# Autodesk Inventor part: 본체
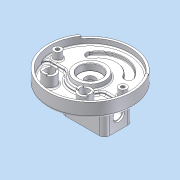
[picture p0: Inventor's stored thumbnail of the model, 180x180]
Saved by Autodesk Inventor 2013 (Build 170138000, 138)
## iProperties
Company: 한국ATC센터
Created: 2015-04
Part Number: 본체
Document SubType Name: Modeling
Designer: KYOUNG IL JANG
Density: 2.71 g/cm^3
Material: 알루미늄 6061
Mass: 1340.83 g
Surface Area: 1387.34 cm^2
Volume: 494.771 cm^3
Author: KYOUNG IL JANG
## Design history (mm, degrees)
sketch "스케치1"
  geometry: L1 (-59, -19)-(-59, 19); L2 (59, 19)-(59, -19); L3 (-41, 19)-(-41, -19); L4 (41, -19)-(41, 19); L5 (38.527, 33.023)-(55.442, 39.179); L6 (-38.527, 33.023)-(-55.442, 39.179); C1 r 90 at (0, 0); C2 r 95 at (0, 0); A1 r 59 centre (0, 19) between (59, 19) and (-59, 19); A2 r 59 centre (0, -19) between (-59, -19) and (59, -19); A3 r 41 centre (0, -19) between (-41, -19) and (41, -19); A4 r 41 centre (0, 19) between (41, 19) and (-41, 19); 2 further points
  constraints: 12 end point, 12 point on circle, 6 centre point, 4 tangent, 2 parallel, 2 point on line, 1 coincident, 1 horizontal alignment, 1 midpoint, 1 vertical, 1 vertical alignment, 3 other
  dimensions: "d2" = 180 diameter of C1; "d3" = 156 dimension on A2 A1; "d4" = 118 distance between parallel lines of L2 L1; "d5" = 18 distance between parallel lines of L2 L4; "d8" = 190 diameter of C2; "d124" = 110 deg dimension on A1.centre point (0, 0) L5.end; "d125" = 140 deg angle of L5 L6
extrude "돌출1" new body sketch "스케치1" distance "d6" = 14; taper "d7" = 0 deg
extrude "돌출2" join sketch "스케치1" distance "d9" = 13; taper "d10" = 0 deg
extrude "돌출3" cut sketch "스케치1" distance "d11" = 7; taper "d12" = 0 deg
sketch "스케치2"
  geometry: C1 r 11.5 at (0, 0); 1 further point
  constraints: 1 centre point, 1 coincident
  dimensions: "d13" = 23 diameter of C1
extrude "돌출4" cut sketch "스케치2" stored distance "d14" = 7; taper "d15" = 0 deg
fillet "모깎기1"
fillet "모깎기2"
sketch "스케치3"
  geometry: L1 (-73.724, 51.622)-(-77.819, 54.49); L2 (73.724, 51.622)-(77.819, 54.49); L3 (0, 0)-(0, -90); A1 r 95 centre (0, 0) between (-77.819, 54.49) and (77.819, 54.49) reference; A2 r 90 centre (0, 0) between (-73.724, 51.622) and (73.724, 51.622) reference; 1 further point
  constraints: 6 end point, 5 point on circle, 1 point on line, 1 vertical, 1 other
  dimensions: "d16" = 250 deg dimension on L2 L1
extrude "돌출5" join sketch "스케치3" distance "d17" = 5; taper "d18" = 0 deg
hole "구멍1" diameter "d21" = 50; stored, may be unused: countersink angle "d25" = 90 deg, drill point angle "d27" = 0 deg; dims "d19" = 10, "d20" = 10, "d22" = 6, "d23" = 4, "d24" = 2, "d26" = 5
fillet "모깎기3" dims "d28" = 0.3
fillet "모깎기5" dims "d30" = 3
sketch "스케치4"
  geometry: C1 r 35 at (0, 0); C2 r 25 at (0, 0); 1 further point
  constraints: 2 centre point, 1 coincident
  dimensions: "d32" = 70 diameter of C1 (derived); "d36" = 10 radial gap between concentric circles of C1 C2
extrude "돌출6" join sketch "스케치4" distance "d33" = 10; taper "d34" = 0 deg
feature "면 기울기2" dims angle "d37" = 10 deg
chamfer "모따기1" distance "d39" = 1; stored, may be unused: second distance "d40" = 2, angle "d41" = 45 deg
fillet "모깎기7" dims "d42" = 5
sketch "스케치5"
  geometry: L1 (-40.249, -12)-(-89.196, -12); L2 (40.249, -12)-(89.196, -12); A1 r 90 centre (0, 0) between (-89.196, -12) and (89.196, -12) reference; A2 r 42 centre (0, 0) between (-40.249, -12) and (40.249, -12); 1 further point
  constraints: 4 end point, 4 point on circle, 1 centre point, 1 collinear, 1 horizontal, 1 point on line
  dimensions: "d43" = 48 radial gap between concentric circles of A1 A2; "d44" = 12 distance from line of point (0, 0) L1
extrude "돌출7" cut sketch "스케치5" stored distance "d45" = 10; taper "d46" = 0 deg
fillet "모깎기8" dims "d47" = 10
chamfer "모따기2" distance "d49" = 1; stored, may be unused: second distance "d50" = 2, angle "d51" = 45 deg
sketch "스케치8"
  geometry: C1 r 9 at (74, 0); C2 r 9 at (-74, 0); A1 r 74 centre (0, 0) between (74, 0) and (-74, 0); 1 further point
  constraints: 3 centre point, 2 horizontal alignment, 2 point on circle, 1 coincident, 1 equal radius
  dimensions: "d64" = 18 diameter of C1; "d65" = 148 diameter of A1
extrude "돌출9" join sketch "스케치8" stored distance "d66" = 5; taper "d67" = 0 deg
sketch "스케치11"
  geometry: C1 r 15 at (40, -52); C2 r 15 at (-40, -52); 1 further point
  constraints: 2 centre point, 1 equal radius, 1 horizontal alignment
  dimensions: "d82" = 52 vertical distance of point (0, 0) C1.centre; "d83" = 30 diameter of C1; "d84" = 80 distance of C2.centre C1.centre; "d85" = 40 horizontal distance of point (0, 0) C1.centre (= 0.5 x d84)
extrude "돌출10" join sketch "스케치11" stored distance "d86" = 10; taper "d87" = 0 deg
node "구멍3"
node "구멍5"
hole "구멍6" diameter "d92" = 20; stored, may be unused: countersink angle "d96" = 90 deg, drill point angle "d98" = 118 deg; dims "d90" = 10, "d91" = 10, "d93" = 6, "d94" = 4, "d95" = 2, "d97" = 8
hole "구멍7" diameter "d101" = 20; stored, may be unused: countersink angle "d105" = 90 deg, drill point angle "d107" = 118 deg; dims "d99" = 10, "d100" = 10, "d102" = 6, "d103" = 4, "d104" = 2, "d106" = 8
fillet "모깎기13" dims "d108" = 3
sketch "스케치13"
  geometry: L1 (-20.252, -58)-(-26, -58); L2 (-42, -58)-(-47.748, -58); L3 (-20.252, -46)-(-26, -46); L4 (-42, -46)-(-47.748, -46); L5 (-108, -65.748)-(-108, -60); L6 (-108, -44)-(-108, -38.252); L7 (-120, -44)-(-120, -38.252); L8 (-120, -60)-(-120, -65.748); A1 r 15 centre (-34, -52) between (-20.252, -58) and (-47.748, -58) reference; A2 r 10 centre (-34, -52) between (-26, -58) and (-42, -58) reference; A3 r 15 centre (-114, -52) between (-108, -65.748) and (-108, -38.252) reference; A4 r 10 centre (-114, -52) between (-108, -60) and (-108, -44) reference; 1 further point
  constraints: 16 end point, 16 point on circle, 3 equal length, 3 point on line, 2 collinear, 1 horizontal, 1 perpendicular
  dimensions: "d114" = 12 distance between parallel lines of L4 L2; "d115" = 6 distance from line of A1.centre L2 (= 0.5 x d114); "d116" = 12 distance between parallel lines of L8 L5 (= d114); "d117" = 6 distance from line of A3.centre L5 (= d115)
extrude "돌출12" join sketch "스케치13" distance "d118" = 3; taper "d119" = 0 deg
fillet "모깎기14" dims "d120" = 1
sketch "스케치14"
  geometry: L1 (23, 32.5)-(-53, 32.5); L2 (-65, 20.5)-(-65, -20.5); L3 (-53, -32.5)-(23, -32.5); L4 (35, -20.5)-(35, 20.5); L5 (30, 20.5)-(30, -20.5); L6 (23, -27.5)-(-53, -27.5); L7 (-60, -20.5)-(-60, 20.5); L8 (-53, 27.5)-(23, 27.5); A1 r 12 centre (-53, -20.5) between (-65, -20.5) and (-53, -32.5); A2 r 12 centre (-53, 20.5) between (-53, 32.5) and (-65, 20.5); A3 r 12 centre (23, 20.5) between (35, 20.5) and (23, 32.5); A4 r 12 centre (23, -20.5) between (23, -32.5) and (35, -20.5); A5 r 7 centre (23, -20.5) between (23, -27.5) and (30, -20.5); A6 r 7 centre (-53, -20.5) between (-60, -20.5) and (-53, -27.5); A7 r 7 centre (-53, 20.5) between (-53, 27.5) and (-60, 20.5); A8 r 7 centre (23, 20.5) between (30, 20.5) and (23, 27.5); A9 r 6 centre (-23, -25) between (-17.546, -27.5) and (-28.454, -27.5); A10 r 6 centre (-23, 25) between (-28.454, 27.5) and (-17.546, 27.5); 6 further points
  constraints: 20 point on circle, 16 end point, 12 point on line, 10 centre point, 8 tangent, 4 equal radius, 4 parallel, 2 perpendicular, 1 horizontal, 1 horizontal alignment, 1 midpoint, 1 vertical alignment, 7 other
  dimensions: "d126" = 35 distance from line of point (0, 0) L4; "d127" = 65 distance of point (35, -32.5) point (35, 32.5); "d128" = 100 distance of point (35, 32.5) point (-65, 32.5); "d132" = 12 radius of A1; "d133" = 5 distance between parallel lines of L5 L4; "d141" = 42 distance from line of A9.centre L2; "d142" = 12 diameter of A9; "d143" = 50 distance of A10.centre A9.centre; "d144" = 25 vertical distance of point (0, 0) A9.centre (= 0.5 x d143)
extrude "돌출13" join sketch "스케치14" distance "d130" = 58; taper "d131" = 0 deg
fillet "모깎기16" dims "d145" = 3
hole "구멍8" diameter "d148" = 4.134; stored, may be unused: countersink angle "d152" = 90 deg, drill point angle "d154" = 118 deg; dims "d146" = 10, "d147" = 10, "d149" = 12, "d150" = 4, "d151" = 2, "d153" = 15
hole "구멍9" diameter "d157" = 4.134; stored, may be unused: countersink angle "d161" = 90 deg, drill point angle "d163" = 118 deg; dims "d155" = 10, "d156" = 10, "d158" = 12, "d159" = 4, "d160" = 2, "d162" = 15
sketch "스케치17"
  geometry: L1 (-58, 110.5)-(-58, -69.5) reference; C1 r 15 at (-29.5, 20.5); 1 further point
  constraints: 1 centre point, 1 horizontal alignment
  dimensions: "d164" = 28.5 distance from line of C1.centre L1; "d165" = 30 diameter of C1
extrude "돌출16" join sketch "스케치17" distance "d166" = 28; taper "d167" = 0 deg
fillet "모깎기17" dims "d168" = 1
hole "구멍10" diameter "d171" = 22; stored, may be unused: countersink angle "d175" = 90 deg, drill point angle "d177" = 118 deg; dims "d169" = 10, "d170" = 10, "d172" = 12, "d173" = 26, "d174" = 4, "d176" = 15
node "솔리드1"
sketch "스케치9"
  geometry: 1 further point
hole "구멍2" sketch "스케치9" diameter "d68" = 8.376; stored, may be unused: countersink angle "d72" = 90 deg, drill point angle "d74" = 120 deg; dims "d69" = 16, "d70" = 4, "d71" = 2, "d73" = 21
sketch "스케치10"
  geometry: 1 further point
hole "구멍4" sketch "스케치10" diameter "d75" = 8.376; stored, may be unused: countersink angle "d79" = 90 deg, drill point angle "d81" = 120 deg; dims "d76" = 16, "d77" = 4, "d78" = 2, "d80" = 21
